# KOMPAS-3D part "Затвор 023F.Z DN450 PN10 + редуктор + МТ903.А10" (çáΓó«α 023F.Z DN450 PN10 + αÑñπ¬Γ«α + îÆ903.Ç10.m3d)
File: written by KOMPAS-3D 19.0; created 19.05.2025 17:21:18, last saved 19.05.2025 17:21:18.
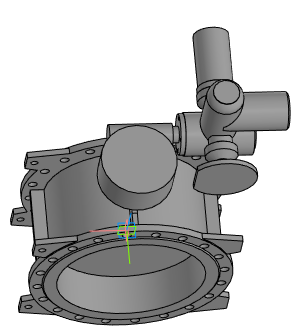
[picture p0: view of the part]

Document properties: Полное имя файла: Затвор 023F.Z DN450 PN10 + редуктор + МТ903.А10.a3d

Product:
- Part/product: Затвор 023F.Z DN450 PN10 + редуктор + МТ903.А10
    Масса: 300.817

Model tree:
1. Операция без истории:1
